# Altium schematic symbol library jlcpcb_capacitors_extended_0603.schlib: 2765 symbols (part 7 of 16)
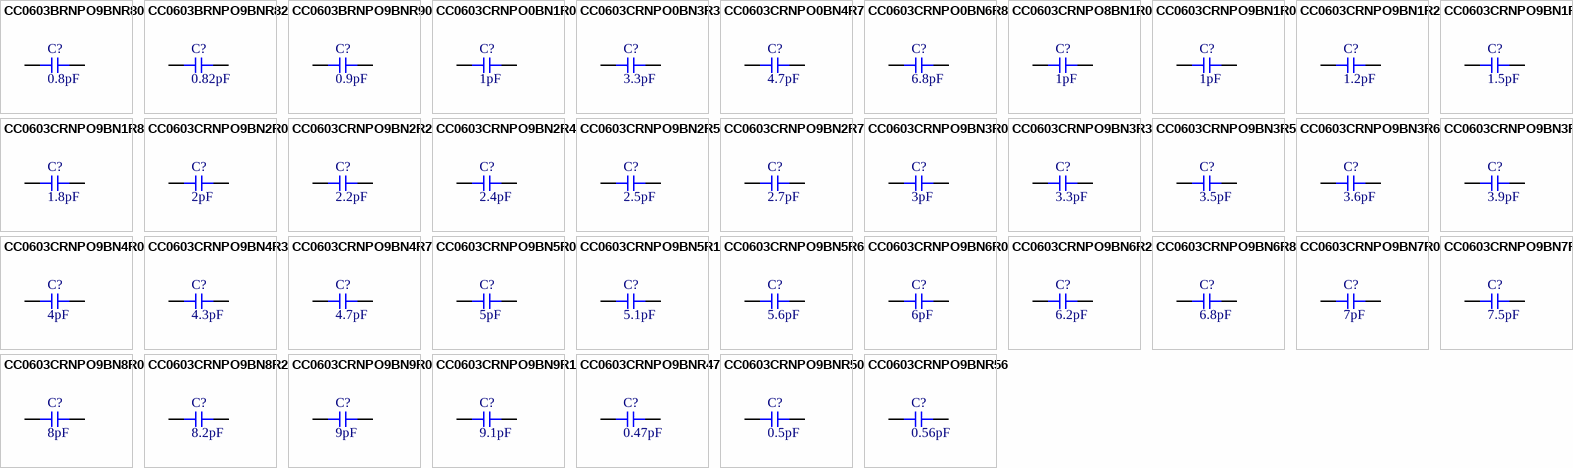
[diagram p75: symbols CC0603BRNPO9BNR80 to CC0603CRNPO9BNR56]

## CC0603CRNPO9BN2R4
designator C?  Capacitance: 2.4pF  (hidden comment: *)
Capacitor, Ceramic (MLCC), 2.4pF, ±0.25pF, 50V, NP0, ±0.25pF, SMD 0603; Manufacturer: YAGEO; Manufacturer Part Number: CC0603CRNPO9BN2R4
footprint CAP-0603 (0603 (1608M) Capacitor)
pins: 1, 2

## CC0603CRNPO9BN2R5
designator C?  Capacitance: 2.5pF  (hidden comment: *)
Capacitor, Ceramic (MLCC), 2.5pF, ±0.25pF, 50V, NP0, ±0.25pF, SMD 0603; Manufacturer: YAGEO; Manufacturer Part Number: CC0603CRNPO9BN2R5
footprint CAP-0603 (0603 (1608M) Capacitor)
pins: 1, 2

## CC0603CRNPO9BN2R7
designator C?  Capacitance: 2.7pF  (hidden comment: *)
Capacitor, Ceramic (MLCC), 2.7pF, ±0.25pF, 50V, NP0, ±0.25pF, SMD 0603; Manufacturer: YAGEO; Manufacturer Part Number: CC0603CRNPO9BN2R7
footprint CAP-0603 (0603 (1608M) Capacitor)
pins: 1, 2

## CC0603CRNPO9BN3R0
designator C?  Capacitance: 3pF  (hidden comment: *)
Capacitor, Ceramic (MLCC), 3pF, ±0.25pF, 50V, NP0, ±0.25pF, SMD 0603; Manufacturer: YAGEO; Manufacturer Part Number: CC0603CRNPO9BN3R0
footprint CAP-0603 (0603 (1608M) Capacitor)
pins: 1, 2

## CC0603CRNPO9BN3R3
designator C?  Capacitance: 3.3pF  (hidden comment: *)
Capacitor, Ceramic (MLCC), 3.3pF, ±0.25pF, 50V, NP0, ±0.25pF, SMD 0603; Manufacturer: YAGEO; Manufacturer Part Number: CC0603CRNPO9BN3R3
footprint CAP-0603 (0603 (1608M) Capacitor)
pins: 1, 2

## CC0603CRNPO9BN3R5
designator C?  Capacitance: 3.5pF  (hidden comment: *)
Capacitor, Ceramic (MLCC), 3.5pF, ±0.25pF, 50V, NP0, ±0.25pF, SMD 0603; Manufacturer: YAGEO; Manufacturer Part Number: CC0603CRNPO9BN3R5
footprint CAP-0603 (0603 (1608M) Capacitor)
pins: 1, 2

## CC0603CRNPO9BN3R6
designator C?  Capacitance: 3.6pF  (hidden comment: *)
Capacitor, Ceramic (MLCC), 3.6pF, ±0.25pF, 50V, NP0, ±0.25pF, SMD 0603; Manufacturer: YAGEO; Manufacturer Part Number: CC0603CRNPO9BN3R6
footprint CAP-0603 (0603 (1608M) Capacitor)
pins: 1, 2

## CC0603CRNPO9BN3R9
designator C?  Capacitance: 3.9pF  (hidden comment: *)
Capacitor, Ceramic (MLCC), 3.9pF, ±0.25pF, 50V, NP0, ±0.25pF, SMD 0603; Manufacturer: YAGEO; Manufacturer Part Number: CC0603CRNPO9BN3R9
footprint CAP-0603 (0603 (1608M) Capacitor)
pins: 1, 2

## CC0603CRNPO9BN4R0
designator C?  Capacitance: 4pF  (hidden comment: *)
Capacitor, Ceramic (MLCC), 4pF, ±0.25pF, 50V, NP0, ±0.25pF, SMD 0603; Manufacturer: YAGEO; Manufacturer Part Number: CC0603CRNPO9BN4R0
footprint CAP-0603 (0603 (1608M) Capacitor)
pins: 1, 2

## CC0603CRNPO9BN4R3
designator C?  Capacitance: 4.3pF  (hidden comment: *)
Capacitor, Ceramic (MLCC), 4.3pF, ±0.25pF, 50V, NP0, ±0.25pF, SMD 0603; Manufacturer: YAGEO; Manufacturer Part Number: CC0603CRNPO9BN4R3
footprint CAP-0603 (0603 (1608M) Capacitor)
pins: 1, 2

## CC0603CRNPO9BN4R7
designator C?  Capacitance: 4.7pF  (hidden comment: *)
Capacitor, Ceramic (MLCC), 4.7pF, ±0.25pF, 50V, NP0, ±0.25pF, SMD 0603; Manufacturer: YAGEO; Manufacturer Part Number: CC0603CRNPO9BN4R7
footprint CAP-0603 (0603 (1608M) Capacitor)
pins: 1, 2

## CC0603CRNPO9BN5R0
designator C?  Capacitance: 5pF  (hidden comment: *)
Capacitor, Ceramic (MLCC), 5pF, ±0.25pF, 50V, NP0, ±0.25pF, SMD 0603; Manufacturer: YAGEO; Manufacturer Part Number: CC0603CRNPO9BN5R0
footprint CAP-0603 (0603 (1608M) Capacitor)
pins: 1, 2

## CC0603CRNPO9BN5R1
designator C?  Capacitance: 5.1pF  (hidden comment: *)
Capacitor, Ceramic (MLCC), 5.1pF, ±0.25pF, 50V, NP0, ±0.25pF, SMD 0603; Manufacturer: YAGEO; Manufacturer Part Number: CC0603CRNPO9BN5R1
footprint CAP-0603 (0603 (1608M) Capacitor)
pins: 1, 2

## CC0603CRNPO9BN5R6
designator C?  Capacitance: 5.6pF  (hidden comment: *)
Capacitor, Ceramic (MLCC), 5.6pF, ±0.25pF, 50V, NP0, ±0.25pF, SMD 0603; Manufacturer: YAGEO; Manufacturer Part Number: CC0603CRNPO9BN5R6
footprint CAP-0603 (0603 (1608M) Capacitor)
pins: 1, 2

## CC0603CRNPO9BN6R0
designator C?  Capacitance: 6pF  (hidden comment: *)
Capacitor, Ceramic (MLCC), 6pF, ±0.25pF, 50V, NP0, ±0.25pF, SMD 0603; Manufacturer: YAGEO; Manufacturer Part Number: CC0603CRNPO9BN6R0
footprint CAP-0603 (0603 (1608M) Capacitor)
pins: 1, 2

## CC0603CRNPO9BN6R2
designator C?  Capacitance: 6.2pF  (hidden comment: *)
Capacitor, Ceramic (MLCC), 6.2pF, ±0.25pF, 50V, NP0, ±0.25pF, SMD 0603; Manufacturer: YAGEO; Manufacturer Part Number: CC0603CRNPO9BN6R2
footprint CAP-0603 (0603 (1608M) Capacitor)
pins: 1, 2

## CC0603CRNPO9BN6R8
designator C?  Capacitance: 6.8pF  (hidden comment: *)
Capacitor, Ceramic (MLCC), 6.8pF, ±0.25pF, 50V, NP0, ±0.25pF, SMD 0603; Manufacturer: YAGEO; Manufacturer Part Number: CC0603CRNPO9BN6R8
footprint CAP-0603 (0603 (1608M) Capacitor)
pins: 1, 2

## CC0603CRNPO9BN7R0
designator C?  Capacitance: 7pF  (hidden comment: *)
Capacitor, Ceramic (MLCC), 7pF, ±0.25pF, 50V, NP0, ±0.25pF, SMD 0603; Manufacturer: YAGEO; Manufacturer Part Number: CC0603CRNPO9BN7R0
footprint CAP-0603 (0603 (1608M) Capacitor)
pins: 1, 2

## CC0603CRNPO9BN7R5
designator C?  Capacitance: 7.5pF  (hidden comment: *)
Capacitor, Ceramic (MLCC), 7.5pF, ±0.25pF, 50V, NP0, ±0.25pF, SMD 0603; Manufacturer: YAGEO; Manufacturer Part Number: CC0603CRNPO9BN7R5
footprint CAP-0603 (0603 (1608M) Capacitor)
pins: 1, 2

## CC0603CRNPO9BN8R0
designator C?  Capacitance: 8pF  (hidden comment: *)
Capacitor, Ceramic (MLCC), 8pF, ±0.25pF, 50V, NP0, ±0.25pF, SMD 0603; Manufacturer: YAGEO; Manufacturer Part Number: CC0603CRNPO9BN8R0
footprint CAP-0603 (0603 (1608M) Capacitor)
pins: 1, 2

## CC0603CRNPO9BN8R2
designator C?  Capacitance: 8.2pF  (hidden comment: *)
Capacitor, Ceramic (MLCC), 8.2pF, ±0.25pF, 50V, NP0, ±0.25pF, SMD 0603; Manufacturer: YAGEO; Manufacturer Part Number: CC0603CRNPO9BN8R2
footprint CAP-0603 (0603 (1608M) Capacitor)
pins: 1, 2

## CC0603CRNPO9BN9R0
designator C?  Capacitance: 9pF  (hidden comment: *)
Capacitor, Ceramic (MLCC), 9pF, ±0.25pF, 50V, NP0, ±0.25pF, SMD 0603; Manufacturer: YAGEO; Manufacturer Part Number: CC0603CRNPO9BN9R0
footprint CAP-0603 (0603 (1608M) Capacitor)
pins: 1, 2

## CC0603CRNPO9BN9R1
designator C?  Capacitance: 9.1pF  (hidden comment: *)
Capacitor, Ceramic (MLCC), 9.1pF, ±0.25pF, 50V, NP0, ±0.25pF, SMD 0603; Manufacturer: YAGEO; Manufacturer Part Number: CC0603CRNPO9BN9R1
footprint CAP-0603 (0603 (1608M) Capacitor)
pins: 1, 2

## CC0603CRNPO9BNR47
designator C?  Capacitance: 0.47pF  (hidden comment: *)
Capacitor, Ceramic (MLCC), 0.47pF, ±0.25pF, 50V, NP0, ±0.25pF, SMD 0603; Manufacturer: YAGEO; Manufacturer Part Number: CC0603CRNPO9BNR47
footprint CAP-0603 (0603 (1608M) Capacitor)
pins: 1, 2

## CC0603CRNPO9BNR50
designator C?  Capacitance: 0.5pF  (hidden comment: *)
Capacitor, Ceramic (MLCC), 0.5pF, ±0.25pF, 50V, NP0, ±0.25pF, SMD 0603; Manufacturer: YAGEO; Manufacturer Part Number: CC0603CRNPO9BNR50
footprint CAP-0603 (0603 (1608M) Capacitor)
pins: 1, 2

## CC0603CRNPO9BNR56
designator C?  Capacitance: 0.56pF  (hidden comment: *)
Capacitor, Ceramic (MLCC), 0.56pF, ±0.25pF, 50V, NP0, ±0.25pF, SMD 0603; Manufacturer: YAGEO; Manufacturer Part Number: CC0603CRNPO9BNR56
footprint CAP-0603 (0603 (1608M) Capacitor)
pins: 1, 2

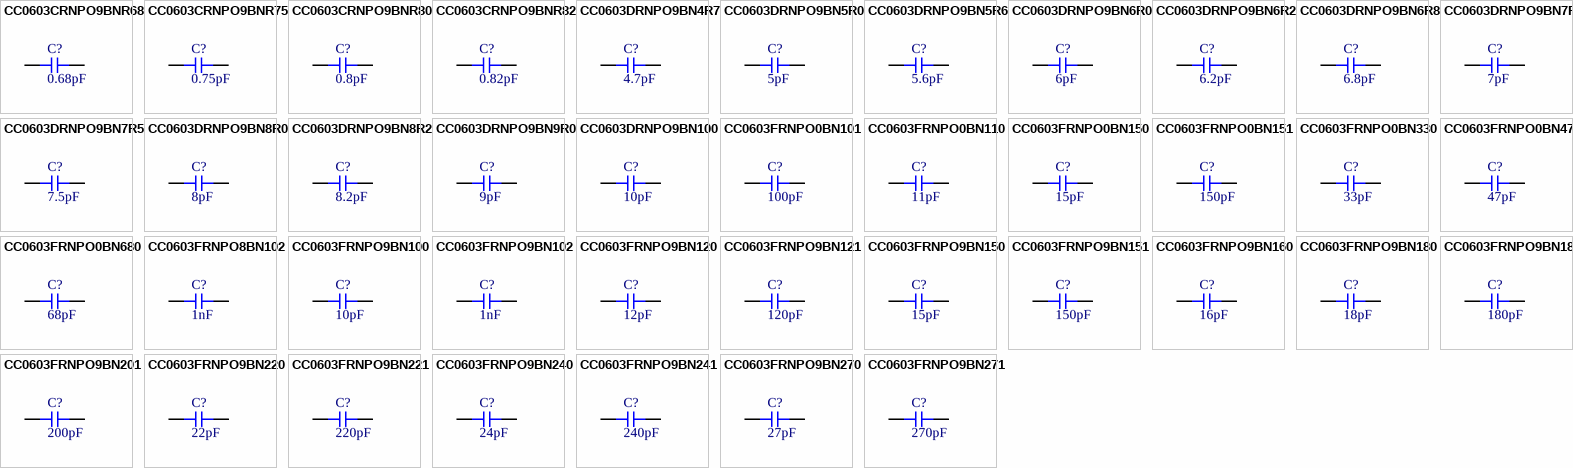
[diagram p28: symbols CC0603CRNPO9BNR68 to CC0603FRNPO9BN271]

## CC0603CRNPO9BNR68
designator C?  Capacitance: 0.68pF  (hidden comment: *)
Capacitor, Ceramic (MLCC), 0.68pF, ±0.25pF, 50V, NP0, ±0.25pF, SMD 0603; Manufacturer: YAGEO; Manufacturer Part Number: CC0603CRNPO9BNR68
footprint CAP-0603 (0603 (1608M) Capacitor)
pins: 1, 2

## CC0603CRNPO9BNR75
designator C?  Capacitance: 0.75pF  (hidden comment: *)
Capacitor, Ceramic (MLCC), 0.75pF, ±0.25pF, 50V, NP0, ±0.25pF, SMD 0603; Manufacturer: YAGEO; Manufacturer Part Number: CC0603CRNPO9BNR75
footprint CAP-0603 (0603 (1608M) Capacitor)
pins: 1, 2

## CC0603CRNPO9BNR80
designator C?  Capacitance: 0.8pF  (hidden comment: *)
Capacitor, Ceramic (MLCC), 0.8pF, ±0.25pF, 50V, NP0, ±0.25pF, SMD 0603; Manufacturer: YAGEO; Manufacturer Part Number: CC0603CRNPO9BNR80
footprint CAP-0603 (0603 (1608M) Capacitor)
pins: 1, 2

## CC0603CRNPO9BNR82
designator C?  Capacitance: 0.82pF  (hidden comment: *)
Capacitor, Ceramic (MLCC), 0.82pF, ±0.25pF, 50V, NP0, ±0.25pF, SMD 0603; Manufacturer: YAGEO; Manufacturer Part Number: CC0603CRNPO9BNR82
footprint CAP-0603 (0603 (1608M) Capacitor)
pins: 1, 2

## CC0603DRNPO9BN4R7
designator C?  Capacitance: 4.7pF  (hidden comment: *)
Capacitor, Ceramic (MLCC), 4.7pF, ±0.5pF, 50V, NP0, ±0.5pF, SMD 0603; Manufacturer: YAGEO; Manufacturer Part Number: CC0603DRNPO9BN4R7
footprint CAP-0603 (0603 (1608M) Capacitor)
pins: 1, 2

## CC0603DRNPO9BN5R0
designator C?  Capacitance: 5pF  (hidden comment: *)
Capacitor, Ceramic (MLCC), 5pF, ±0.5pF, 50V, NP0, ±0.5pF, SMD 0603; Manufacturer: YAGEO; Manufacturer Part Number: CC0603DRNPO9BN5R0
footprint CAP-0603 (0603 (1608M) Capacitor)
pins: 1, 2

## CC0603DRNPO9BN5R6
designator C?  Capacitance: 5.6pF  (hidden comment: *)
Capacitor, Ceramic (MLCC), 5.6pF, ±0.5pF, 50V, NP0, ±0.5pF, SMD 0603; Manufacturer: YAGEO; Manufacturer Part Number: CC0603DRNPO9BN5R6
footprint CAP-0603 (0603 (1608M) Capacitor)
pins: 1, 2

## CC0603DRNPO9BN6R0
designator C?  Capacitance: 6pF  (hidden comment: *)
Capacitor, Ceramic (MLCC), 6pF, ±0.5pF, 50V, NP0, ±0.5pF, SMD 0603; Manufacturer: YAGEO; Manufacturer Part Number: CC0603DRNPO9BN6R0
footprint CAP-0603 (0603 (1608M) Capacitor)
pins: 1, 2

## CC0603DRNPO9BN6R2
designator C?  Capacitance: 6.2pF  (hidden comment: *)
Capacitor, Ceramic (MLCC), 6.2pF, ±0.5pF, 50V, NP0, ±0.5pF, SMD 0603; Manufacturer: YAGEO; Manufacturer Part Number: CC0603DRNPO9BN6R2
footprint CAP-0603 (0603 (1608M) Capacitor)
pins: 1, 2

## CC0603DRNPO9BN6R8
designator C?  Capacitance: 6.8pF  (hidden comment: *)
Capacitor, Ceramic (MLCC), 6.8pF, ±0.5pF, 50V, NP0, ±0.5pF, SMD 0603; Manufacturer: YAGEO; Manufacturer Part Number: CC0603DRNPO9BN6R8
footprint CAP-0603 (0603 (1608M) Capacitor)
pins: 1, 2

## CC0603DRNPO9BN7R0
designator C?  Capacitance: 7pF  (hidden comment: *)
Capacitor, Ceramic (MLCC), 7pF, ±0.5pF, 50V, NP0, ±0.5pF, SMD 0603; Manufacturer: YAGEO; Manufacturer Part Number: CC0603DRNPO9BN7R0
footprint CAP-0603 (0603 (1608M) Capacitor)
pins: 1, 2

## CC0603DRNPO9BN7R5
designator C?  Capacitance: 7.5pF  (hidden comment: *)
Capacitor, Ceramic (MLCC), 7.5pF, ±0.5pF, 50V, NP0, ±0.5pF, SMD 0603; Manufacturer: YAGEO; Manufacturer Part Number: CC0603DRNPO9BN7R5
footprint CAP-0603 (0603 (1608M) Capacitor)
pins: 1, 2

## CC0603DRNPO9BN8R0
designator C?  Capacitance: 8pF  (hidden comment: *)
Capacitor, Ceramic (MLCC), 8pF, ±0.5pF, 50V, NP0, ±0.5pF, SMD 0603; Manufacturer: YAGEO; Manufacturer Part Number: CC0603DRNPO9BN8R0
footprint CAP-0603 (0603 (1608M) Capacitor)
pins: 1, 2

## CC0603DRNPO9BN8R2
designator C?  Capacitance: 8.2pF  (hidden comment: *)
Capacitor, Ceramic (MLCC), 8.2pF, ±0.5pF, 50V, NP0, ±0.5pF, SMD 0603; Manufacturer: YAGEO; Manufacturer Part Number: CC0603DRNPO9BN8R2
footprint CAP-0603 (0603 (1608M) Capacitor)
pins: 1, 2

## CC0603DRNPO9BN9R0
designator C?  Capacitance: 9pF  (hidden comment: *)
Capacitor, Ceramic (MLCC), 9pF, ±0.5pF, 50V, NP0, ±0.5pF, SMD 0603; Manufacturer: YAGEO; Manufacturer Part Number: CC0603DRNPO9BN9R0
footprint CAP-0603 (0603 (1608M) Capacitor)
pins: 1, 2

## CC0603DRNPO9BN100
designator C?  Capacitance: 10pF  (hidden comment: *)
Capacitor, Ceramic (MLCC), 10pF, ±0.5pF, 50V, NP0, ±0.5pF, SMD 0603; Manufacturer: YAGEO; Manufacturer Part Number: CC0603DRNPO9BN100
footprint CAP-0603 (0603 (1608M) Capacitor)
pins: 1, 2

## CC0603FRNPO0BN101
designator C?  Capacitance: 100pF  (hidden comment: *)
Capacitor, Ceramic (MLCC), 100pF, ±1%, 100V, NP0, ±1%, SMD 0603; Manufacturer: YAGEO; Manufacturer Part Number: CC0603FRNPO0BN101
footprint CAP-0603 (0603 (1608M) Capacitor)
pins: 1, 2

## CC0603FRNPO0BN110
designator C?  Capacitance: 11pF  (hidden comment: *)
Capacitor, Ceramic (MLCC), 11pF, ±1%, 100V, NP0, ±1%, SMD 0603; Manufacturer: YAGEO; Manufacturer Part Number: CC0603FRNPO0BN110
footprint CAP-0603 (0603 (1608M) Capacitor)
pins: 1, 2

## CC0603FRNPO0BN150
designator C?  Capacitance: 15pF  (hidden comment: *)
Capacitor, Ceramic (MLCC), 15pF, ±1%, 100V, NP0, ±1%, SMD 0603; Manufacturer: YAGEO; Manufacturer Part Number: CC0603FRNPO0BN150
footprint CAP-0603 (0603 (1608M) Capacitor)
pins: 1, 2

## CC0603FRNPO0BN151
designator C?  Capacitance: 150pF  (hidden comment: *)
Capacitor, Ceramic (MLCC), 150pF, ±1%, 100V, NP0, ±1%, SMD 0603; Manufacturer: YAGEO; Manufacturer Part Number: CC0603FRNPO0BN151
footprint CAP-0603 (0603 (1608M) Capacitor)
pins: 1, 2

## CC0603FRNPO0BN330
designator C?  Capacitance: 33pF  (hidden comment: *)
Capacitor, Ceramic (MLCC), 33pF, ±1%, 100V, NP0, ±1%, SMD 0603; Manufacturer: YAGEO; Manufacturer Part Number: CC0603FRNPO0BN330
footprint CAP-0603 (0603 (1608M) Capacitor)
pins: 1, 2

## CC0603FRNPO0BN470
designator C?  Capacitance: 47pF  (hidden comment: *)
Capacitor, Ceramic (MLCC), 47pF, ±1%, 100V, NP0, ±1%, SMD 0603; Manufacturer: YAGEO; Manufacturer Part Number: CC0603FRNPO0BN470
footprint CAP-0603 (0603 (1608M) Capacitor)
pins: 1, 2

## CC0603FRNPO0BN680
designator C?  Capacitance: 68pF  (hidden comment: *)
Capacitor, Ceramic (MLCC), 68pF, ±1%, 100V, NP0, ±1%, SMD 0603; Manufacturer: YAGEO; Manufacturer Part Number: CC0603FRNPO0BN680
footprint CAP-0603 (0603 (1608M) Capacitor)
pins: 1, 2

## CC0603FRNPO8BN102
designator C?  Capacitance: 1nF  (hidden comment: *)
Capacitor, Ceramic (MLCC), 1nF, ±1%, 25V, NP0, ±1%, SMD 0603; Manufacturer: YAGEO; Manufacturer Part Number: CC0603FRNPO8BN102
footprint CAP-0603 (0603 (1608M) Capacitor)
pins: 1, 2

## CC0603FRNPO9BN100
designator C?  Capacitance: 10pF  (hidden comment: *)
Capacitor, Ceramic (MLCC), 10pF, ±1%, 50V, NP0, ±1%, SMD 0603; Manufacturer: YAGEO; Manufacturer Part Number: CC0603FRNPO9BN100
footprint CAP-0603 (0603 (1608M) Capacitor)
pins: 1, 2

## CC0603FRNPO9BN102
designator C?  Capacitance: 1nF  (hidden comment: *)
Capacitor, Ceramic (MLCC), 1nF, ±1%, 50V, NP0, ±1%, SMD 0603; Manufacturer: YAGEO; Manufacturer Part Number: CC0603FRNPO9BN102
footprint CAP-0603 (0603 (1608M) Capacitor)
pins: 1, 2

## CC0603FRNPO9BN120
designator C?  Capacitance: 12pF  (hidden comment: *)
Capacitor, Ceramic (MLCC), 12pF, ±1%, 50V, NP0, ±1%, SMD 0603; Manufacturer: YAGEO; Manufacturer Part Number: CC0603FRNPO9BN120
footprint CAP-0603 (0603 (1608M) Capacitor)
pins: 1, 2

## CC0603FRNPO9BN121
designator C?  Capacitance: 120pF  (hidden comment: *)
Capacitor, Ceramic (MLCC), 120pF, ±1%, 50V, NP0, ±1%, SMD 0603; Manufacturer: YAGEO; Manufacturer Part Number: CC0603FRNPO9BN121
footprint CAP-0603 (0603 (1608M) Capacitor)
pins: 1, 2

## CC0603FRNPO9BN150
designator C?  Capacitance: 15pF  (hidden comment: *)
Capacitor, Ceramic (MLCC), 15pF, ±1%, 50V, NP0, ±1%, SMD 0603; Manufacturer: YAGEO; Manufacturer Part Number: CC0603FRNPO9BN150
footprint CAP-0603 (0603 (1608M) Capacitor)
pins: 1, 2

## CC0603FRNPO9BN151
designator C?  Capacitance: 150pF  (hidden comment: *)
Capacitor, Ceramic (MLCC), 150pF, ±1%, 50V, NP0, ±1%, SMD 0603; Manufacturer: YAGEO; Manufacturer Part Number: CC0603FRNPO9BN151
footprint CAP-0603 (0603 (1608M) Capacitor)
pins: 1, 2

## CC0603FRNPO9BN160
designator C?  Capacitance: 16pF  (hidden comment: *)
Capacitor, Ceramic (MLCC), 16pF, ±1%, 50V, NP0, ±1%, SMD 0603; Manufacturer: YAGEO; Manufacturer Part Number: CC0603FRNPO9BN160
footprint CAP-0603 (0603 (1608M) Capacitor)
pins: 1, 2

## CC0603FRNPO9BN180
designator C?  Capacitance: 18pF  (hidden comment: *)
Capacitor, Ceramic (MLCC), 18pF, ±1%, 50V, NP0, ±1%, SMD 0603; Manufacturer: YAGEO; Manufacturer Part Number: CC0603FRNPO9BN180
footprint CAP-0603 (0603 (1608M) Capacitor)
pins: 1, 2

## CC0603FRNPO9BN181
designator C?  Capacitance: 180pF  (hidden comment: *)
Capacitor, Ceramic (MLCC), 180pF, ±1%, 50V, NP0, ±1%, SMD 0603; Manufacturer: YAGEO; Manufacturer Part Number: CC0603FRNPO9BN181
footprint CAP-0603 (0603 (1608M) Capacitor)
pins: 1, 2

## CC0603FRNPO9BN201
designator C?  Capacitance: 200pF  (hidden comment: *)
Capacitor, Ceramic (MLCC), 200pF, ±1%, 50V, NP0, ±1%, SMD 0603; Manufacturer: YAGEO; Manufacturer Part Number: CC0603FRNPO9BN201
footprint CAP-0603 (0603 (1608M) Capacitor)
pins: 1, 2

## CC0603FRNPO9BN220
designator C?  Capacitance: 22pF  (hidden comment: *)
Capacitor, Ceramic (MLCC), 22pF, ±1%, 50V, NP0, ±1%, SMD 0603; Manufacturer: YAGEO; Manufacturer Part Number: CC0603FRNPO9BN220
footprint CAP-0603 (0603 (1608M) Capacitor)
pins: 1, 2

## CC0603FRNPO9BN221
designator C?  Capacitance: 220pF  (hidden comment: *)
Capacitor, Ceramic (MLCC), 220pF, ±1%, 50V, NP0, ±1%, SMD 0603; Manufacturer: YAGEO; Manufacturer Part Number: CC0603FRNPO9BN221
footprint CAP-0603 (0603 (1608M) Capacitor)
pins: 1, 2

## CC0603FRNPO9BN240
designator C?  Capacitance: 24pF  (hidden comment: *)
Capacitor, Ceramic (MLCC), 24pF, ±1%, 50V, NP0, ±1%, SMD 0603; Manufacturer: YAGEO; Manufacturer Part Number: CC0603FRNPO9BN240
footprint CAP-0603 (0603 (1608M) Capacitor)
pins: 1, 2

## CC0603FRNPO9BN241
designator C?  Capacitance: 240pF  (hidden comment: *)
Capacitor, Ceramic (MLCC), 240pF, ±1%, 50V, NP0, ±1%, SMD 0603; Manufacturer: YAGEO; Manufacturer Part Number: CC0603FRNPO9BN241
footprint CAP-0603 (0603 (1608M) Capacitor)
pins: 1, 2

## CC0603FRNPO9BN270
designator C?  Capacitance: 27pF  (hidden comment: *)
Capacitor, Ceramic (MLCC), 27pF, ±1%, 50V, NP0, ±1%, SMD 0603; Manufacturer: YAGEO; Manufacturer Part Number: CC0603FRNPO9BN270
footprint CAP-0603 (0603 (1608M) Capacitor)
pins: 1, 2

## CC0603FRNPO9BN271
designator C?  Capacitance: 270pF  (hidden comment: *)
Capacitor, Ceramic (MLCC), 270pF, ±1%, 50V, NP0, ±1%, SMD 0603; Manufacturer: YAGEO; Manufacturer Part Number: CC0603FRNPO9BN271
footprint CAP-0603 (0603 (1608M) Capacitor)
pins: 1, 2

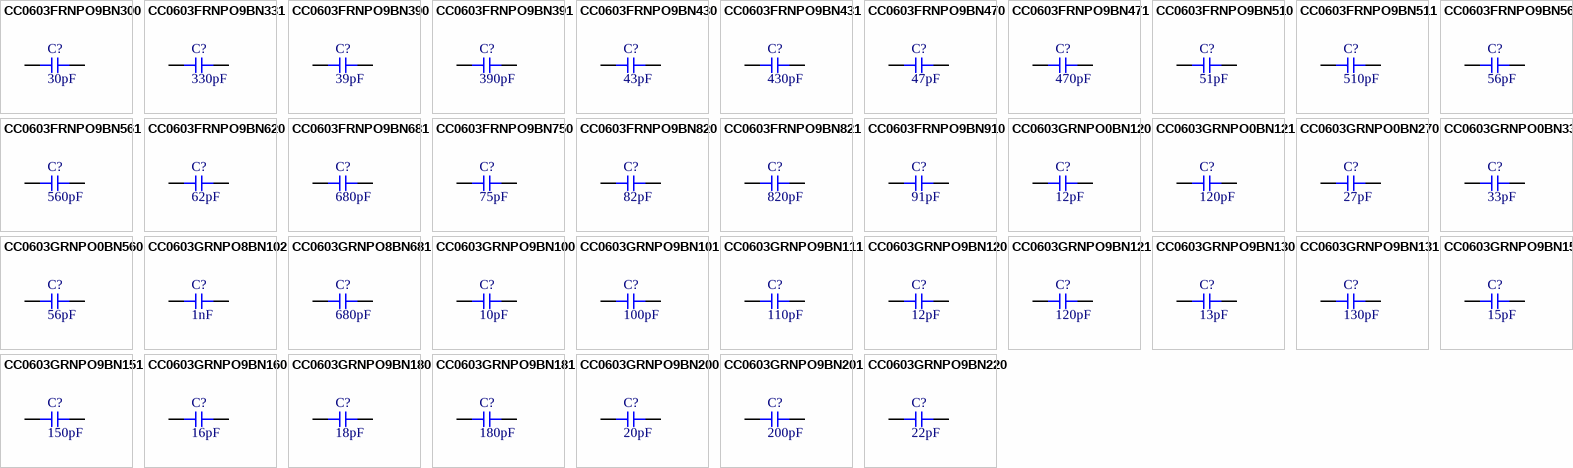
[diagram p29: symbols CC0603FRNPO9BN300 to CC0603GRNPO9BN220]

## CC0603FRNPO9BN300
designator C?  Capacitance: 30pF  (hidden comment: *)
Capacitor, Ceramic (MLCC), 30pF, ±1%, 50V, NP0, ±1%, SMD 0603; Manufacturer: YAGEO; Manufacturer Part Number: CC0603FRNPO9BN300
footprint CAP-0603 (0603 (1608M) Capacitor)
pins: 1, 2

## CC0603FRNPO9BN331
designator C?  Capacitance: 330pF  (hidden comment: *)
Capacitor, Ceramic (MLCC), 330pF, ±1%, 50V, NP0, ±1%, SMD 0603; Manufacturer: YAGEO; Manufacturer Part Number: CC0603FRNPO9BN331
footprint CAP-0603 (0603 (1608M) Capacitor)
pins: 1, 2

## CC0603FRNPO9BN390
designator C?  Capacitance: 39pF  (hidden comment: *)
Capacitor, Ceramic (MLCC), 39pF, ±1%, 50V, NP0, ±1%, SMD 0603; Manufacturer: YAGEO; Manufacturer Part Number: CC0603FRNPO9BN390
footprint CAP-0603 (0603 (1608M) Capacitor)
pins: 1, 2

## CC0603FRNPO9BN391
designator C?  Capacitance: 390pF  (hidden comment: *)
Capacitor, Ceramic (MLCC), 390pF, ±1%, 50V, NP0, ±1%, SMD 0603; Manufacturer: YAGEO; Manufacturer Part Number: CC0603FRNPO9BN391
footprint CAP-0603 (0603 (1608M) Capacitor)
pins: 1, 2

## CC0603FRNPO9BN430
designator C?  Capacitance: 43pF  (hidden comment: *)
Capacitor, Ceramic (MLCC), 43pF, ±1%, 50V, NP0, ±1%, SMD 0603; Manufacturer: YAGEO; Manufacturer Part Number: CC0603FRNPO9BN430
footprint CAP-0603 (0603 (1608M) Capacitor)
pins: 1, 2

## CC0603FRNPO9BN431
designator C?  Capacitance: 430pF  (hidden comment: *)
Capacitor, Ceramic (MLCC), 430pF, ±1%, 50V, NP0, ±1%, SMD 0603; Manufacturer: YAGEO; Manufacturer Part Number: CC0603FRNPO9BN431
footprint CAP-0603 (0603 (1608M) Capacitor)
pins: 1, 2

## CC0603FRNPO9BN470
designator C?  Capacitance: 47pF  (hidden comment: *)
Capacitor, Ceramic (MLCC), 47pF, ±1%, 50V, NP0, ±1%, SMD 0603; Manufacturer: YAGEO; Manufacturer Part Number: CC0603FRNPO9BN470
footprint CAP-0603 (0603 (1608M) Capacitor)
pins: 1, 2

## CC0603FRNPO9BN471
designator C?  Capacitance: 470pF  (hidden comment: *)
Capacitor, Ceramic (MLCC), 470pF, ±1%, 50V, NP0, ±1%, SMD 0603; Manufacturer: YAGEO; Manufacturer Part Number: CC0603FRNPO9BN471
footprint CAP-0603 (0603 (1608M) Capacitor)
pins: 1, 2

## CC0603FRNPO9BN510
designator C?  Capacitance: 51pF  (hidden comment: *)
Capacitor, Ceramic (MLCC), 51pF, ±1%, 50V, NP0, ±1%, SMD 0603; Manufacturer: YAGEO; Manufacturer Part Number: CC0603FRNPO9BN510
footprint CAP-0603 (0603 (1608M) Capacitor)
pins: 1, 2

## CC0603FRNPO9BN511
designator C?  Capacitance: 510pF  (hidden comment: *)
Capacitor, Ceramic (MLCC), 510pF, ±1%, 50V, NP0, ±1%, SMD 0603; Manufacturer: YAGEO; Manufacturer Part Number: CC0603FRNPO9BN511
footprint CAP-0603 (0603 (1608M) Capacitor)
pins: 1, 2

## CC0603FRNPO9BN560
designator C?  Capacitance: 56pF  (hidden comment: *)
Capacitor, Ceramic (MLCC), 56pF, ±1%, 50V, NP0, ±1%, SMD 0603; Manufacturer: YAGEO; Manufacturer Part Number: CC0603FRNPO9BN560
footprint CAP-0603 (0603 (1608M) Capacitor)
pins: 1, 2

## CC0603FRNPO9BN561
designator C?  Capacitance: 560pF  (hidden comment: *)
Capacitor, Ceramic (MLCC), 560pF, ±1%, 50V, NP0, ±1%, SMD 0603; Manufacturer: YAGEO; Manufacturer Part Number: CC0603FRNPO9BN561
footprint CAP-0603 (0603 (1608M) Capacitor)
pins: 1, 2

## CC0603FRNPO9BN620
designator C?  Capacitance: 62pF  (hidden comment: *)
Capacitor, Ceramic (MLCC), 62pF, ±1%, 50V, NP0, ±1%, SMD 0603; Manufacturer: YAGEO; Manufacturer Part Number: CC0603FRNPO9BN620
footprint CAP-0603 (0603 (1608M) Capacitor)
pins: 1, 2

## CC0603FRNPO9BN681
designator C?  Capacitance: 680pF  (hidden comment: *)
Capacitor, Ceramic (MLCC), 680pF, ±1%, 50V, NP0, ±1%, SMD 0603; Manufacturer: YAGEO; Manufacturer Part Number: CC0603FRNPO9BN681
footprint CAP-0603 (0603 (1608M) Capacitor)
pins: 1, 2

## CC0603FRNPO9BN750
designator C?  Capacitance: 75pF  (hidden comment: *)
Capacitor, Ceramic (MLCC), 75pF, ±1%, 50V, NP0, ±1%, SMD 0603; Manufacturer: YAGEO; Manufacturer Part Number: CC0603FRNPO9BN750
footprint CAP-0603 (0603 (1608M) Capacitor)
pins: 1, 2

## CC0603FRNPO9BN820
designator C?  Capacitance: 82pF  (hidden comment: *)
Capacitor, Ceramic (MLCC), 82pF, ±1%, 50V, NP0, ±1%, SMD 0603; Manufacturer: YAGEO; Manufacturer Part Number: CC0603FRNPO9BN820
footprint CAP-0603 (0603 (1608M) Capacitor)
pins: 1, 2

## CC0603FRNPO9BN821
designator C?  Capacitance: 820pF  (hidden comment: *)
Capacitor, Ceramic (MLCC), 820pF, ±1%, 50V, NP0, ±1%, SMD 0603; Manufacturer: YAGEO; Manufacturer Part Number: CC0603FRNPO9BN821
footprint CAP-0603 (0603 (1608M) Capacitor)
pins: 1, 2

## CC0603FRNPO9BN910
designator C?  Capacitance: 91pF  (hidden comment: *)
Capacitor, Ceramic (MLCC), 91pF, ±1%, 50V, NP0, ±1%, SMD 0603; Manufacturer: YAGEO; Manufacturer Part Number: CC0603FRNPO9BN910
footprint CAP-0603 (0603 (1608M) Capacitor)
pins: 1, 2

## CC0603GRNPO0BN120
designator C?  Capacitance: 12pF  (hidden comment: *)
Capacitor, Ceramic (MLCC), 12pF, ±2%, 100V, NP0, ±2%, SMD 0603; Manufacturer: YAGEO; Manufacturer Part Number: CC0603GRNPO0BN120
footprint CAP-0603 (0603 (1608M) Capacitor)
pins: 1, 2

## CC0603GRNPO0BN121
designator C?  Capacitance: 120pF  (hidden comment: *)
Capacitor, Ceramic (MLCC), 120pF, ±2%, 100V, NP0, ±2%, SMD 0603; Manufacturer: YAGEO; Manufacturer Part Number: CC0603GRNPO0BN121
footprint CAP-0603 (0603 (1608M) Capacitor)
pins: 1, 2

## CC0603GRNPO0BN270
designator C?  Capacitance: 27pF  (hidden comment: *)
Capacitor, Ceramic (MLCC), 27pF, ±2%, 100V, NP0, ±2%, SMD 0603; Manufacturer: YAGEO; Manufacturer Part Number: CC0603GRNPO0BN270
footprint CAP-0603 (0603 (1608M) Capacitor)
pins: 1, 2

## CC0603GRNPO0BN330
designator C?  Capacitance: 33pF  (hidden comment: *)
Capacitor, Ceramic (MLCC), 33pF, ±2%, 100V, NP0, ±2%, SMD 0603; Manufacturer: YAGEO; Manufacturer Part Number: CC0603GRNPO0BN330
footprint CAP-0603 (0603 (1608M) Capacitor)
pins: 1, 2

## CC0603GRNPO0BN560
designator C?  Capacitance: 56pF  (hidden comment: *)
Capacitor, Ceramic (MLCC), 56pF, ±2%, 100V, NP0, ±2%, SMD 0603; Manufacturer: YAGEO; Manufacturer Part Number: CC0603GRNPO0BN560
footprint CAP-0603 (0603 (1608M) Capacitor)
pins: 1, 2

## CC0603GRNPO8BN102
designator C?  Capacitance: 1nF  (hidden comment: *)
Capacitor, Ceramic (MLCC), 1nF, ±2%, 25V, NP0, ±2%, SMD 0603; Manufacturer: YAGEO; Manufacturer Part Number: CC0603GRNPO8BN102
footprint CAP-0603 (0603 (1608M) Capacitor)
pins: 1, 2

## CC0603GRNPO8BN681
designator C?  Capacitance: 680pF  (hidden comment: *)
Capacitor, Ceramic (MLCC), 680pF, ±2%, 25V, NP0, ±2%, SMD 0603; Manufacturer: YAGEO; Manufacturer Part Number: CC0603GRNPO8BN681
footprint CAP-0603 (0603 (1608M) Capacitor)
pins: 1, 2

## CC0603GRNPO9BN100
designator C?  Capacitance: 10pF  (hidden comment: *)
Capacitor, Ceramic (MLCC), 10pF, ±2%, 50V, NP0, ±2%, SMD 0603; Manufacturer: YAGEO; Manufacturer Part Number: CC0603GRNPO9BN100
footprint CAP-0603 (0603 (1608M) Capacitor)
pins: 1, 2

## CC0603GRNPO9BN101
designator C?  Capacitance: 100pF  (hidden comment: *)
Capacitor, Ceramic (MLCC), 100pF, ±2%, 50V, NP0, ±2%, SMD 0603; Manufacturer: YAGEO; Manufacturer Part Number: CC0603GRNPO9BN101
footprint CAP-0603 (0603 (1608M) Capacitor)
pins: 1, 2

## CC0603GRNPO9BN111
designator C?  Capacitance: 110pF  (hidden comment: *)
Capacitor, Ceramic (MLCC), 110pF, ±2%, 50V, NP0, ±2%, SMD 0603; Manufacturer: YAGEO; Manufacturer Part Number: CC0603GRNPO9BN111
footprint CAP-0603 (0603 (1608M) Capacitor)
pins: 1, 2

## CC0603GRNPO9BN120
designator C?  Capacitance: 12pF  (hidden comment: *)
Capacitor, Ceramic (MLCC), 12pF, ±2%, 50V, NP0, ±2%, SMD 0603; Manufacturer: YAGEO; Manufacturer Part Number: CC0603GRNPO9BN120
footprint CAP-0603 (0603 (1608M) Capacitor)
pins: 1, 2

## CC0603GRNPO9BN121
designator C?  Capacitance: 120pF  (hidden comment: *)
Capacitor, Ceramic (MLCC), 120pF, ±2%, 50V, NP0, ±2%, SMD 0603; Manufacturer: YAGEO; Manufacturer Part Number: CC0603GRNPO9BN121
footprint CAP-0603 (0603 (1608M) Capacitor)
pins: 1, 2

## CC0603GRNPO9BN130
designator C?  Capacitance: 13pF  (hidden comment: *)
Capacitor, Ceramic (MLCC), 13pF, ±2%, 50V, NP0, ±2%, SMD 0603; Manufacturer: YAGEO; Manufacturer Part Number: CC0603GRNPO9BN130
footprint CAP-0603 (0603 (1608M) Capacitor)
pins: 1, 2

## CC0603GRNPO9BN131
designator C?  Capacitance: 130pF  (hidden comment: *)
Capacitor, Ceramic (MLCC), 130pF, ±2%, 50V, NP0, ±2%, SMD 0603; Manufacturer: YAGEO; Manufacturer Part Number: CC0603GRNPO9BN131
footprint CAP-0603 (0603 (1608M) Capacitor)
pins: 1, 2

## CC0603GRNPO9BN150
designator C?  Capacitance: 15pF  (hidden comment: *)
Capacitor, Ceramic (MLCC), 15pF, ±2%, 50V, NP0, ±2%, SMD 0603; Manufacturer: YAGEO; Manufacturer Part Number: CC0603GRNPO9BN150
footprint CAP-0603 (0603 (1608M) Capacitor)
pins: 1, 2

## CC0603GRNPO9BN151
designator C?  Capacitance: 150pF  (hidden comment: *)
Capacitor, Ceramic (MLCC), 150pF, ±2%, 50V, NP0, ±2%, SMD 0603; Manufacturer: YAGEO; Manufacturer Part Number: CC0603GRNPO9BN151
footprint CAP-0603 (0603 (1608M) Capacitor)
pins: 1, 2

## CC0603GRNPO9BN160
designator C?  Capacitance: 16pF  (hidden comment: *)
Capacitor, Ceramic (MLCC), 16pF, ±2%, 50V, NP0, ±2%, SMD 0603; Manufacturer: YAGEO; Manufacturer Part Number: CC0603GRNPO9BN160
footprint CAP-0603 (0603 (1608M) Capacitor)
pins: 1, 2

## CC0603GRNPO9BN180
designator C?  Capacitance: 18pF  (hidden comment: *)
Capacitor, Ceramic (MLCC), 18pF, ±2%, 50V, NP0, ±2%, SMD 0603; Manufacturer: YAGEO; Manufacturer Part Number: CC0603GRNPO9BN180
footprint CAP-0603 (0603 (1608M) Capacitor)
pins: 1, 2

## CC0603GRNPO9BN181
designator C?  Capacitance: 180pF  (hidden comment: *)
Capacitor, Ceramic (MLCC), 180pF, ±2%, 50V, NP0, ±2%, SMD 0603; Manufacturer: YAGEO; Manufacturer Part Number: CC0603GRNPO9BN181
footprint CAP-0603 (0603 (1608M) Capacitor)
pins: 1, 2

## CC0603GRNPO9BN200
designator C?  Capacitance: 20pF  (hidden comment: *)
Capacitor, Ceramic (MLCC), 20pF, ±2%, 50V, NP0, ±2%, SMD 0603; Manufacturer: YAGEO; Manufacturer Part Number: CC0603GRNPO9BN200
footprint CAP-0603 (0603 (1608M) Capacitor)
pins: 1, 2

## CC0603GRNPO9BN201
designator C?  Capacitance: 200pF  (hidden comment: *)
Capacitor, Ceramic (MLCC), 200pF, ±2%, 50V, NP0, ±2%, SMD 0603; Manufacturer: YAGEO; Manufacturer Part Number: CC0603GRNPO9BN201
footprint CAP-0603 (0603 (1608M) Capacitor)
pins: 1, 2

## CC0603GRNPO9BN220
designator C?  Capacitance: 22pF  (hidden comment: *)
Capacitor, Ceramic (MLCC), 22pF, ±2%, 50V, NP0, ±2%, SMD 0603; Manufacturer: YAGEO; Manufacturer Part Number: CC0603GRNPO9BN220
footprint CAP-0603 (0603 (1608M) Capacitor)
pins: 1, 2

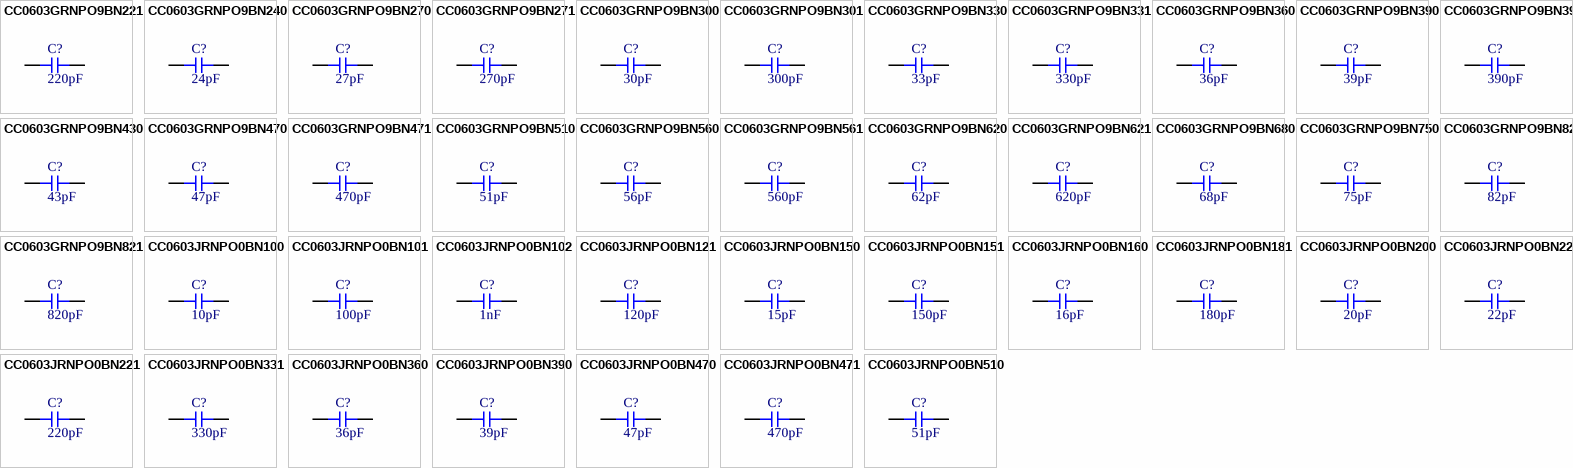
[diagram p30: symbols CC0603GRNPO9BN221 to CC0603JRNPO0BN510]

## CC0603GRNPO9BN221
designator C?  Capacitance: 220pF  (hidden comment: *)
Capacitor, Ceramic (MLCC), 220pF, ±2%, 50V, NP0, ±2%, SMD 0603; Manufacturer: YAGEO; Manufacturer Part Number: CC0603GRNPO9BN221
footprint CAP-0603 (0603 (1608M) Capacitor)
pins: 1, 2

## CC0603GRNPO9BN240
designator C?  Capacitance: 24pF  (hidden comment: *)
Capacitor, Ceramic (MLCC), 24pF, ±2%, 50V, NP0, ±2%, SMD 0603; Manufacturer: YAGEO; Manufacturer Part Number: CC0603GRNPO9BN240
footprint CAP-0603 (0603 (1608M) Capacitor)
pins: 1, 2

## CC0603GRNPO9BN270
designator C?  Capacitance: 27pF  (hidden comment: *)
Capacitor, Ceramic (MLCC), 27pF, ±2%, 50V, NP0, ±2%, SMD 0603; Manufacturer: YAGEO; Manufacturer Part Number: CC0603GRNPO9BN270
footprint CAP-0603 (0603 (1608M) Capacitor)
pins: 1, 2

## CC0603GRNPO9BN271
designator C?  Capacitance: 270pF  (hidden comment: *)
Capacitor, Ceramic (MLCC), 270pF, ±2%, 50V, NP0, ±2%, SMD 0603; Manufacturer: YAGEO; Manufacturer Part Number: CC0603GRNPO9BN271
footprint CAP-0603 (0603 (1608M) Capacitor)
pins: 1, 2

## CC0603GRNPO9BN300
designator C?  Capacitance: 30pF  (hidden comment: *)
Capacitor, Ceramic (MLCC), 30pF, ±2%, 50V, NP0, ±2%, SMD 0603; Manufacturer: YAGEO; Manufacturer Part Number: CC0603GRNPO9BN300
footprint CAP-0603 (0603 (1608M) Capacitor)
pins: 1, 2

## CC0603GRNPO9BN301
designator C?  Capacitance: 300pF  (hidden comment: *)
Capacitor, Ceramic (MLCC), 300pF, ±2%, 50V, NP0, ±2%, SMD 0603; Manufacturer: YAGEO; Manufacturer Part Number: CC0603GRNPO9BN301
footprint CAP-0603 (0603 (1608M) Capacitor)
pins: 1, 2

## CC0603GRNPO9BN330
designator C?  Capacitance: 33pF  (hidden comment: *)
Capacitor, Ceramic (MLCC), 33pF, ±2%, 50V, NP0, ±2%, SMD 0603; Manufacturer: YAGEO; Manufacturer Part Number: CC0603GRNPO9BN330
footprint CAP-0603 (0603 (1608M) Capacitor)
pins: 1, 2

## CC0603GRNPO9BN331
designator C?  Capacitance: 330pF  (hidden comment: *)
Capacitor, Ceramic (MLCC), 330pF, ±2%, 50V, NP0, ±2%, SMD 0603; Manufacturer: YAGEO; Manufacturer Part Number: CC0603GRNPO9BN331
footprint CAP-0603 (0603 (1608M) Capacitor)
pins: 1, 2

## CC0603GRNPO9BN360
designator C?  Capacitance: 36pF  (hidden comment: *)
Capacitor, Ceramic (MLCC), 36pF, ±2%, 50V, NP0, ±2%, SMD 0603; Manufacturer: YAGEO; Manufacturer Part Number: CC0603GRNPO9BN360
footprint CAP-0603 (0603 (1608M) Capacitor)
pins: 1, 2

## CC0603GRNPO9BN390
designator C?  Capacitance: 39pF  (hidden comment: *)
Capacitor, Ceramic (MLCC), 39pF, ±2%, 50V, NP0, ±2%, SMD 0603; Manufacturer: YAGEO; Manufacturer Part Number: CC0603GRNPO9BN390
footprint CAP-0603 (0603 (1608M) Capacitor)
pins: 1, 2

## CC0603GRNPO9BN391
designator C?  Capacitance: 390pF  (hidden comment: *)
Capacitor, Ceramic (MLCC), 390pF, ±2%, 50V, NP0, ±2%, SMD 0603; Manufacturer: YAGEO; Manufacturer Part Number: CC0603GRNPO9BN391
footprint CAP-0603 (0603 (1608M) Capacitor)
pins: 1, 2

## CC0603GRNPO9BN430
designator C?  Capacitance: 43pF  (hidden comment: *)
Capacitor, Ceramic (MLCC), 43pF, ±2%, 50V, NP0, ±2%, SMD 0603; Manufacturer: YAGEO; Manufacturer Part Number: CC0603GRNPO9BN430
footprint CAP-0603 (0603 (1608M) Capacitor)
pins: 1, 2

## CC0603GRNPO9BN470
designator C?  Capacitance: 47pF  (hidden comment: *)
Capacitor, Ceramic (MLCC), 47pF, ±2%, 50V, NP0, ±2%, SMD 0603; Manufacturer: YAGEO; Manufacturer Part Number: CC0603GRNPO9BN470
footprint CAP-0603 (0603 (1608M) Capacitor)
pins: 1, 2

## CC0603GRNPO9BN471
designator C?  Capacitance: 470pF  (hidden comment: *)
Capacitor, Ceramic (MLCC), 470pF, ±2%, 50V, NP0, ±2%, SMD 0603; Manufacturer: YAGEO; Manufacturer Part Number: CC0603GRNPO9BN471
footprint CAP-0603 (0603 (1608M) Capacitor)
pins: 1, 2

## CC0603GRNPO9BN510
designator C?  Capacitance: 51pF  (hidden comment: *)
Capacitor, Ceramic (MLCC), 51pF, ±2%, 50V, NP0, ±2%, SMD 0603; Manufacturer: YAGEO; Manufacturer Part Number: CC0603GRNPO9BN510
footprint CAP-0603 (0603 (1608M) Capacitor)
pins: 1, 2

## CC0603GRNPO9BN560
designator C?  Capacitance: 56pF  (hidden comment: *)
Capacitor, Ceramic (MLCC), 56pF, ±2%, 50V, NP0, ±2%, SMD 0603; Manufacturer: YAGEO; Manufacturer Part Number: CC0603GRNPO9BN560
footprint CAP-0603 (0603 (1608M) Capacitor)
pins: 1, 2

## CC0603GRNPO9BN561
designator C?  Capacitance: 560pF  (hidden comment: *)
Capacitor, Ceramic (MLCC), 560pF, ±2%, 50V, NP0, ±2%, SMD 0603; Manufacturer: YAGEO; Manufacturer Part Number: CC0603GRNPO9BN561
footprint CAP-0603 (0603 (1608M) Capacitor)
pins: 1, 2

## CC0603GRNPO9BN620
designator C?  Capacitance: 62pF  (hidden comment: *)
Capacitor, Ceramic (MLCC), 62pF, ±2%, 50V, NP0, ±2%, SMD 0603; Manufacturer: YAGEO; Manufacturer Part Number: CC0603GRNPO9BN620
footprint CAP-0603 (0603 (1608M) Capacitor)
pins: 1, 2

## CC0603GRNPO9BN621
designator C?  Capacitance: 620pF  (hidden comment: *)
Capacitor, Ceramic (MLCC), 620pF, ±2%, 50V, NP0, ±2%, SMD 0603; Manufacturer: YAGEO; Manufacturer Part Number: CC0603GRNPO9BN621
footprint CAP-0603 (0603 (1608M) Capacitor)
pins: 1, 2

## CC0603GRNPO9BN680
designator C?  Capacitance: 68pF  (hidden comment: *)
Capacitor, Ceramic (MLCC), 68pF, ±2%, 50V, NP0, ±2%, SMD 0603; Manufacturer: YAGEO; Manufacturer Part Number: CC0603GRNPO9BN680
footprint CAP-0603 (0603 (1608M) Capacitor)
pins: 1, 2

## CC0603GRNPO9BN750
designator C?  Capacitance: 75pF  (hidden comment: *)
Capacitor, Ceramic (MLCC), 75pF, ±2%, 50V, NP0, ±2%, SMD 0603; Manufacturer: YAGEO; Manufacturer Part Number: CC0603GRNPO9BN750
footprint CAP-0603 (0603 (1608M) Capacitor)
pins: 1, 2

## CC0603GRNPO9BN820
designator C?  Capacitance: 82pF  (hidden comment: *)
Capacitor, Ceramic (MLCC), 82pF, ±2%, 50V, NP0, ±2%, SMD 0603; Manufacturer: YAGEO; Manufacturer Part Number: CC0603GRNPO9BN820
footprint CAP-0603 (0603 (1608M) Capacitor)
pins: 1, 2

## CC0603GRNPO9BN821
designator C?  Capacitance: 820pF  (hidden comment: *)
Capacitor, Ceramic (MLCC), 820pF, ±2%, 50V, NP0, ±2%, SMD 0603; Manufacturer: YAGEO; Manufacturer Part Number: CC0603GRNPO9BN821
footprint CAP-0603 (0603 (1608M) Capacitor)
pins: 1, 2

## CC0603JRNPO0BN100
designator C?  Capacitance: 10pF  (hidden comment: *)
Capacitor, Ceramic (MLCC), 10pF, ±5%, 100V, NP0, ±5%, SMD 0603; Manufacturer: YAGEO; Manufacturer Part Number: CC0603JRNPO0BN100
footprint CAP-0603 (0603 (1608M) Capacitor)
pins: 1, 2

## CC0603JRNPO0BN101
designator C?  Capacitance: 100pF  (hidden comment: *)
Capacitor, Ceramic (MLCC), 100pF, ±5%, 100V, NP0, ±5%, SMD 0603; Manufacturer: YAGEO; Manufacturer Part Number: CC0603JRNPO0BN101
footprint CAP-0603 (0603 (1608M) Capacitor)
pins: 1, 2

## CC0603JRNPO0BN102
designator C?  Capacitance: 1nF  (hidden comment: *)
Capacitor, Ceramic (MLCC), 1nF, ±5%, 100V, NP0, ±5%, SMD 0603; Manufacturer: YAGEO; Manufacturer Part Number: CC0603JRNPO0BN102
footprint CAP-0603 (0603 (1608M) Capacitor)
pins: 1, 2

## CC0603JRNPO0BN121
designator C?  Capacitance: 120pF  (hidden comment: *)
Capacitor, Ceramic (MLCC), 120pF, ±5%, 100V, NP0, ±5%, SMD 0603; Manufacturer: YAGEO; Manufacturer Part Number: CC0603JRNPO0BN121
footprint CAP-0603 (0603 (1608M) Capacitor)
pins: 1, 2

## CC0603JRNPO0BN150
designator C?  Capacitance: 15pF  (hidden comment: *)
Capacitor, Ceramic (MLCC), 15pF, ±5%, 100V, NP0, ±5%, SMD 0603; Manufacturer: YAGEO; Manufacturer Part Number: CC0603JRNPO0BN150
footprint CAP-0603 (0603 (1608M) Capacitor)
pins: 1, 2

## CC0603JRNPO0BN151
designator C?  Capacitance: 150pF  (hidden comment: *)
Capacitor, Ceramic (MLCC), 150pF, ±5%, 100V, NP0, ±5%, SMD 0603; Manufacturer: YAGEO; Manufacturer Part Number: CC0603JRNPO0BN151
footprint CAP-0603 (0603 (1608M) Capacitor)
pins: 1, 2

## CC0603JRNPO0BN160
designator C?  Capacitance: 16pF  (hidden comment: *)
Capacitor, Ceramic (MLCC), 16pF, ±5%, 100V, NP0, ±5%, SMD 0603; Manufacturer: YAGEO; Manufacturer Part Number: CC0603JRNPO0BN160
footprint CAP-0603 (0603 (1608M) Capacitor)
pins: 1, 2

## CC0603JRNPO0BN181
designator C?  Capacitance: 180pF  (hidden comment: *)
Capacitor, Ceramic (MLCC), 180pF, ±5%, 100V, NP0, ±5%, SMD 0603; Manufacturer: YAGEO; Manufacturer Part Number: CC0603JRNPO0BN181
footprint CAP-0603 (0603 (1608M) Capacitor)
pins: 1, 2

## CC0603JRNPO0BN200
designator C?  Capacitance: 20pF  (hidden comment: *)
Capacitor, Ceramic (MLCC), 20pF, ±5%, 100V, NP0, ±5%, SMD 0603; Manufacturer: YAGEO; Manufacturer Part Number: CC0603JRNPO0BN200
footprint CAP-0603 (0603 (1608M) Capacitor)
pins: 1, 2

## CC0603JRNPO0BN220
designator C?  Capacitance: 22pF  (hidden comment: *)
Capacitor, Ceramic (MLCC), 22pF, ±5%, 100V, NP0, ±5%, SMD 0603; Manufacturer: YAGEO; Manufacturer Part Number: CC0603JRNPO0BN220
footprint CAP-0603 (0603 (1608M) Capacitor)
pins: 1, 2

## CC0603JRNPO0BN221
designator C?  Capacitance: 220pF  (hidden comment: *)
Capacitor, Ceramic (MLCC), 220pF, ±5%, 100V, NP0, ±5%, SMD 0603; Manufacturer: YAGEO; Manufacturer Part Number: CC0603JRNPO0BN221
footprint CAP-0603 (0603 (1608M) Capacitor)
pins: 1, 2

## CC0603JRNPO0BN331
designator C?  Capacitance: 330pF  (hidden comment: *)
Capacitor, Ceramic (MLCC), 330pF, ±5%, 100V, NP0, ±5%, SMD 0603; Manufacturer: YAGEO; Manufacturer Part Number: CC0603JRNPO0BN331
footprint CAP-0603 (0603 (1608M) Capacitor)
pins: 1, 2

## CC0603JRNPO0BN360
designator C?  Capacitance: 36pF  (hidden comment: *)
Capacitor, Ceramic (MLCC), 36pF, ±5%, 100V, NP0, ±5%, SMD 0603; Manufacturer: YAGEO; Manufacturer Part Number: CC0603JRNPO0BN360
footprint CAP-0603 (0603 (1608M) Capacitor)
pins: 1, 2

## CC0603JRNPO0BN390
designator C?  Capacitance: 39pF  (hidden comment: *)
Capacitor, Ceramic (MLCC), 39pF, ±5%, 100V, NP0, ±5%, SMD 0603; Manufacturer: YAGEO; Manufacturer Part Number: CC0603JRNPO0BN390
footprint CAP-0603 (0603 (1608M) Capacitor)
pins: 1, 2

## CC0603JRNPO0BN470
designator C?  Capacitance: 47pF  (hidden comment: *)
Capacitor, Ceramic (MLCC), 47pF, ±5%, 100V, NP0, ±5%, SMD 0603; Manufacturer: YAGEO; Manufacturer Part Number: CC0603JRNPO0BN470
footprint CAP-0603 (0603 (1608M) Capacitor)
pins: 1, 2

## CC0603JRNPO0BN471
designator C?  Capacitance: 470pF  (hidden comment: *)
Capacitor, Ceramic (MLCC), 470pF, ±5%, 100V, NP0, ±5%, SMD 0603; Manufacturer: YAGEO; Manufacturer Part Number: CC0603JRNPO0BN471
footprint CAP-0603 (0603 (1608M) Capacitor)
pins: 1, 2

## CC0603JRNPO0BN510
designator C?  Capacitance: 51pF  (hidden comment: *)
Capacitor, Ceramic (MLCC), 51pF, ±5%, 100V, NP0, ±5%, SMD 0603; Manufacturer: YAGEO; Manufacturer Part Number: CC0603JRNPO0BN510
footprint CAP-0603 (0603 (1608M) Capacitor)
pins: 1, 2

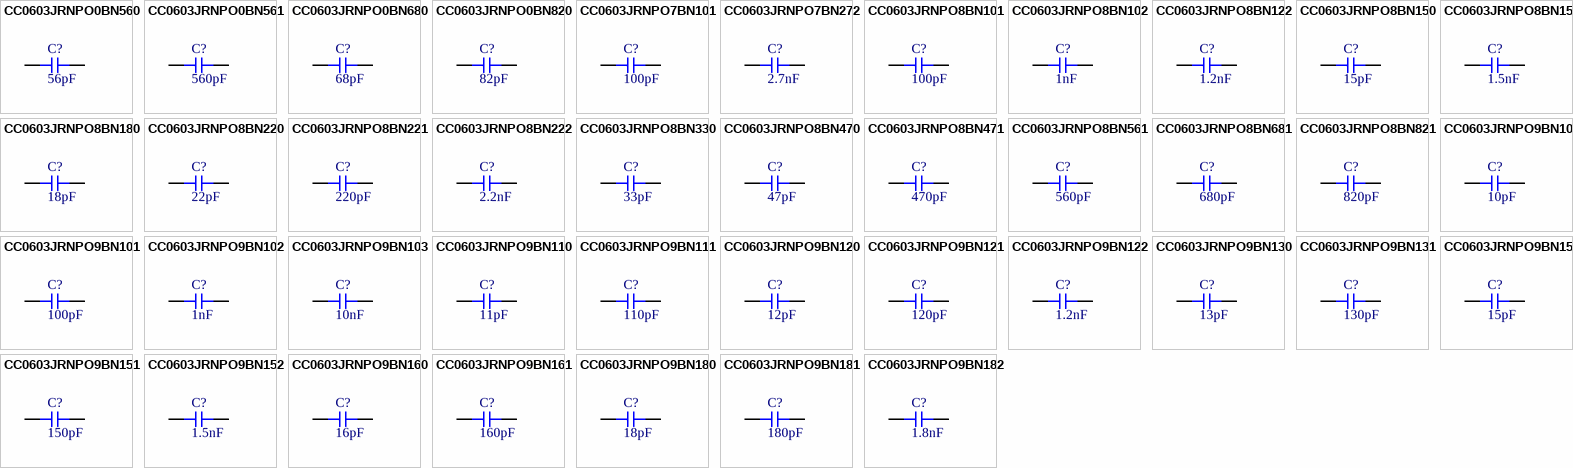
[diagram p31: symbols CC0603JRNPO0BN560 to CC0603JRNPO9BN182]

## CC0603JRNPO0BN560
designator C?  Capacitance: 56pF  (hidden comment: *)
Capacitor, Ceramic (MLCC), 56pF, ±5%, 100V, NP0, ±5%, SMD 0603; Manufacturer: YAGEO; Manufacturer Part Number: CC0603JRNPO0BN560
footprint CAP-0603 (0603 (1608M) Capacitor)
pins: 1, 2

## CC0603JRNPO0BN561
designator C?  Capacitance: 560pF  (hidden comment: *)
Capacitor, Ceramic (MLCC), 560pF, ±5%, 100V, NP0, ±5%, SMD 0603; Manufacturer: YAGEO; Manufacturer Part Number: CC0603JRNPO0BN561
footprint CAP-0603 (0603 (1608M) Capacitor)
pins: 1, 2

## CC0603JRNPO0BN680
designator C?  Capacitance: 68pF  (hidden comment: *)
Capacitor, Ceramic (MLCC), 68pF, ±5%, 100V, NP0, ±5%, SMD 0603; Manufacturer: YAGEO; Manufacturer Part Number: CC0603JRNPO0BN680
footprint CAP-0603 (0603 (1608M) Capacitor)
pins: 1, 2

## CC0603JRNPO0BN820
designator C?  Capacitance: 82pF  (hidden comment: *)
Capacitor, Ceramic (MLCC), 82pF, ±5%, 100V, NP0, ±5%, SMD 0603; Manufacturer: YAGEO; Manufacturer Part Number: CC0603JRNPO0BN820
footprint CAP-0603 (0603 (1608M) Capacitor)
pins: 1, 2

## CC0603JRNPO7BN101
designator C?  Capacitance: 100pF  (hidden comment: *)
Capacitor, Ceramic (MLCC), 100pF, ±5%, 16V, NP0, ±5%, SMD 0603; Manufacturer: YAGEO; Manufacturer Part Number: CC0603JRNPO7BN101
footprint CAP-0603 (0603 (1608M) Capacitor)
pins: 1, 2

## CC0603JRNPO7BN272
designator C?  Capacitance: 2.7nF  (hidden comment: *)
Capacitor, Ceramic (MLCC), 2.7nF, ±5%, 16V, NP0, ±5%, SMD 0603; Manufacturer: YAGEO; Manufacturer Part Number: CC0603JRNPO7BN272
footprint CAP-0603 (0603 (1608M) Capacitor)
pins: 1, 2

## CC0603JRNPO8BN101
designator C?  Capacitance: 100pF  (hidden comment: *)
Capacitor, Ceramic (MLCC), 100pF, ±5%, 25V, NP0, ±5%, SMD 0603; Manufacturer: YAGEO; Manufacturer Part Number: CC0603JRNPO8BN101
footprint CAP-0603 (0603 (1608M) Capacitor)
pins: 1, 2

## CC0603JRNPO8BN102
designator C?  Capacitance: 1nF  (hidden comment: *)
Capacitor, Ceramic (MLCC), 1nF, ±5%, 25V, NP0, ±5%, SMD 0603; Manufacturer: YAGEO; Manufacturer Part Number: CC0603JRNPO8BN102
footprint CAP-0603 (0603 (1608M) Capacitor)
pins: 1, 2

## CC0603JRNPO8BN122
designator C?  Capacitance: 1.2nF  (hidden comment: *)
Capacitor, Ceramic (MLCC), 1.2nF, ±5%, 25V, NP0, ±5%, SMD 0603; Manufacturer: YAGEO; Manufacturer Part Number: CC0603JRNPO8BN122
footprint CAP-0603 (0603 (1608M) Capacitor)
pins: 1, 2

## CC0603JRNPO8BN150
designator C?  Capacitance: 15pF  (hidden comment: *)
Capacitor, Ceramic (MLCC), 15pF, ±5%, 25V, NP0, ±5%, SMD 0603; Manufacturer: YAGEO; Manufacturer Part Number: CC0603JRNPO8BN150
footprint CAP-0603 (0603 (1608M) Capacitor)
pins: 1, 2

## CC0603JRNPO8BN152
designator C?  Capacitance: 1.5nF  (hidden comment: *)
Capacitor, Ceramic (MLCC), 1.5nF, ±5%, 25V, NP0, ±5%, SMD 0603; Manufacturer: YAGEO; Manufacturer Part Number: CC0603JRNPO8BN152
footprint CAP-0603 (0603 (1608M) Capacitor)
pins: 1, 2

## CC0603JRNPO8BN180
designator C?  Capacitance: 18pF  (hidden comment: *)
Capacitor, Ceramic (MLCC), 18pF, ±5%, 25V, NP0, ±5%, SMD 0603; Manufacturer: YAGEO; Manufacturer Part Number: CC0603JRNPO8BN180
footprint CAP-0603 (0603 (1608M) Capacitor)
pins: 1, 2

## CC0603JRNPO8BN220
designator C?  Capacitance: 22pF  (hidden comment: *)
Capacitor, Ceramic (MLCC), 22pF, ±5%, 25V, NP0, ±5%, SMD 0603; Manufacturer: YAGEO; Manufacturer Part Number: CC0603JRNPO8BN220
footprint CAP-0603 (0603 (1608M) Capacitor)
pins: 1, 2

## CC0603JRNPO8BN221
designator C?  Capacitance: 220pF  (hidden comment: *)
Capacitor, Ceramic (MLCC), 220pF, ±5%, 25V, NP0, ±5%, SMD 0603; Manufacturer: YAGEO; Manufacturer Part Number: CC0603JRNPO8BN221
footprint CAP-0603 (0603 (1608M) Capacitor)
pins: 1, 2

## CC0603JRNPO8BN222
designator C?  Capacitance: 2.2nF  (hidden comment: *)
Capacitor, Ceramic (MLCC), 2.2nF, ±5%, 25V, NP0, ±5%, SMD 0603; Manufacturer: YAGEO; Manufacturer Part Number: CC0603JRNPO8BN222
footprint CAP-0603 (0603 (1608M) Capacitor)
pins: 1, 2

## CC0603JRNPO8BN330
designator C?  Capacitance: 33pF  (hidden comment: *)
Capacitor, Ceramic (MLCC), 33pF, ±5%, 25V, NP0, ±5%, SMD 0603; Manufacturer: YAGEO; Manufacturer Part Number: CC0603JRNPO8BN330
footprint CAP-0603 (0603 (1608M) Capacitor)
pins: 1, 2

## CC0603JRNPO8BN470
designator C?  Capacitance: 47pF  (hidden comment: *)
Capacitor, Ceramic (MLCC), 47pF, ±5%, 25V, NP0, ±5%, SMD 0603; Manufacturer: YAGEO; Manufacturer Part Number: CC0603JRNPO8BN470
footprint CAP-0603 (0603 (1608M) Capacitor)
pins: 1, 2

## CC0603JRNPO8BN471
designator C?  Capacitance: 470pF  (hidden comment: *)
Capacitor, Ceramic (MLCC), 470pF, ±5%, 25V, NP0, ±5%, SMD 0603; Manufacturer: YAGEO; Manufacturer Part Number: CC0603JRNPO8BN471
footprint CAP-0603 (0603 (1608M) Capacitor)
pins: 1, 2

## CC0603JRNPO8BN561
designator C?  Capacitance: 560pF  (hidden comment: *)
Capacitor, Ceramic (MLCC), 560pF, ±5%, 25V, NP0, ±5%, SMD 0603; Manufacturer: YAGEO; Manufacturer Part Number: CC0603JRNPO8BN561
footprint CAP-0603 (0603 (1608M) Capacitor)
pins: 1, 2

## CC0603JRNPO8BN681
designator C?  Capacitance: 680pF  (hidden comment: *)
Capacitor, Ceramic (MLCC), 680pF, ±5%, 25V, NP0, ±5%, SMD 0603; Manufacturer: YAGEO; Manufacturer Part Number: CC0603JRNPO8BN681
footprint CAP-0603 (0603 (1608M) Capacitor)
pins: 1, 2

## CC0603JRNPO8BN821
designator C?  Capacitance: 820pF  (hidden comment: *)
Capacitor, Ceramic (MLCC), 820pF, ±5%, 25V, NP0, ±5%, SMD 0603; Manufacturer: YAGEO; Manufacturer Part Number: CC0603JRNPO8BN821
footprint CAP-0603 (0603 (1608M) Capacitor)
pins: 1, 2

## CC0603JRNPO9BN100
designator C?  Capacitance: 10pF  (hidden comment: *)
Capacitor, Ceramic (MLCC), 10pF, ±5%, 50V, NP0, ±5%, SMD 0603; Manufacturer: YAGEO; Manufacturer Part Number: CC0603JRNPO9BN100
footprint CAP-0603 (0603 (1608M) Capacitor)
pins: 1, 2

## CC0603JRNPO9BN101
designator C?  Capacitance: 100pF  (hidden comment: *)
Capacitor, Ceramic (MLCC), 100pF, ±5%, 50V, NP0, ±5%, SMD 0603; Manufacturer: YAGEO; Manufacturer Part Number: CC0603JRNPO9BN101
footprint CAP-0603 (0603 (1608M) Capacitor)
pins: 1, 2

## CC0603JRNPO9BN102
designator C?  Capacitance: 1nF  (hidden comment: *)
Capacitor, Ceramic (MLCC), 1nF, ±5%, 50V, NP0, ±5%, SMD 0603; Manufacturer: YAGEO; Manufacturer Part Number: CC0603JRNPO9BN102
footprint CAP-0603 (0603 (1608M) Capacitor)
pins: 1, 2

## CC0603JRNPO9BN103
designator C?  Capacitance: 10nF  (hidden comment: *)
Capacitor, Ceramic (MLCC), 10nF, ±5%, 50V, NP0, ±5%, SMD 0603; Manufacturer: YAGEO; Manufacturer Part Number: CC0603JRNPO9BN103
footprint CAP-0603 (0603 (1608M) Capacitor)
pins: 1, 2

## CC0603JRNPO9BN110
designator C?  Capacitance: 11pF  (hidden comment: *)
Capacitor, Ceramic (MLCC), 11pF, ±5%, 50V, NP0, ±5%, SMD 0603; Manufacturer: YAGEO; Manufacturer Part Number: CC0603JRNPO9BN110
footprint CAP-0603 (0603 (1608M) Capacitor)
pins: 1, 2

## CC0603JRNPO9BN111
designator C?  Capacitance: 110pF  (hidden comment: *)
Capacitor, Ceramic (MLCC), 110pF, ±5%, 50V, NP0, ±5%, SMD 0603; Manufacturer: YAGEO; Manufacturer Part Number: CC0603JRNPO9BN111
footprint CAP-0603 (0603 (1608M) Capacitor)
pins: 1, 2

## CC0603JRNPO9BN120
designator C?  Capacitance: 12pF  (hidden comment: *)
Capacitor, Ceramic (MLCC), 12pF, ±5%, 50V, NP0, ±5%, SMD 0603; Manufacturer: YAGEO; Manufacturer Part Number: CC0603JRNPO9BN120
footprint CAP-0603 (0603 (1608M) Capacitor)
pins: 1, 2

## CC0603JRNPO9BN121
designator C?  Capacitance: 120pF  (hidden comment: *)
Capacitor, Ceramic (MLCC), 120pF, ±5%, 50V, NP0, ±5%, SMD 0603; Manufacturer: YAGEO; Manufacturer Part Number: CC0603JRNPO9BN121
footprint CAP-0603 (0603 (1608M) Capacitor)
pins: 1, 2

## CC0603JRNPO9BN122
designator C?  Capacitance: 1.2nF  (hidden comment: *)
Capacitor, Ceramic (MLCC), 1.2nF, ±5%, 50V, NP0, ±5%, SMD 0603; Manufacturer: YAGEO; Manufacturer Part Number: CC0603JRNPO9BN122
footprint CAP-0603 (0603 (1608M) Capacitor)
pins: 1, 2

## CC0603JRNPO9BN130
designator C?  Capacitance: 13pF  (hidden comment: *)
Capacitor, Ceramic (MLCC), 13pF, ±5%, 50V, NP0, ±5%, SMD 0603; Manufacturer: YAGEO; Manufacturer Part Number: CC0603JRNPO9BN130
footprint CAP-0603 (0603 (1608M) Capacitor)
pins: 1, 2

## CC0603JRNPO9BN131
designator C?  Capacitance: 130pF  (hidden comment: *)
Capacitor, Ceramic (MLCC), 130pF, ±5%, 50V, NP0, ±5%, SMD 0603; Manufacturer: YAGEO; Manufacturer Part Number: CC0603JRNPO9BN131
footprint CAP-0603 (0603 (1608M) Capacitor)
pins: 1, 2

## CC0603JRNPO9BN150
designator C?  Capacitance: 15pF  (hidden comment: *)
Capacitor, Ceramic (MLCC), 15pF, ±5%, 50V, NP0, ±5%, SMD 0603; Manufacturer: YAGEO; Manufacturer Part Number: CC0603JRNPO9BN150
footprint CAP-0603 (0603 (1608M) Capacitor)
pins: 1, 2

## CC0603JRNPO9BN151
designator C?  Capacitance: 150pF  (hidden comment: *)
Capacitor, Ceramic (MLCC), 150pF, ±5%, 50V, NP0, ±5%, SMD 0603; Manufacturer: YAGEO; Manufacturer Part Number: CC0603JRNPO9BN151
footprint CAP-0603 (0603 (1608M) Capacitor)
pins: 1, 2

## CC0603JRNPO9BN152
designator C?  Capacitance: 1.5nF  (hidden comment: *)
Capacitor, Ceramic (MLCC), 1.5nF, ±5%, 50V, NP0, ±5%, SMD 0603; Manufacturer: YAGEO; Manufacturer Part Number: CC0603JRNPO9BN152
footprint CAP-0603 (0603 (1608M) Capacitor)
pins: 1, 2

## CC0603JRNPO9BN160
designator C?  Capacitance: 16pF  (hidden comment: *)
Capacitor, Ceramic (MLCC), 16pF, ±5%, 50V, NP0, ±5%, SMD 0603; Manufacturer: YAGEO; Manufacturer Part Number: CC0603JRNPO9BN160
footprint CAP-0603 (0603 (1608M) Capacitor)
pins: 1, 2

## CC0603JRNPO9BN161
designator C?  Capacitance: 160pF  (hidden comment: *)
Capacitor, Ceramic (MLCC), 160pF, ±5%, 50V, NP0, ±5%, SMD 0603; Manufacturer: YAGEO; Manufacturer Part Number: CC0603JRNPO9BN161
footprint CAP-0603 (0603 (1608M) Capacitor)
pins: 1, 2

## CC0603JRNPO9BN180
designator C?  Capacitance: 18pF  (hidden comment: *)
Capacitor, Ceramic (MLCC), 18pF, ±5%, 50V, NP0, ±5%, SMD 0603; Manufacturer: YAGEO; Manufacturer Part Number: CC0603JRNPO9BN180
footprint CAP-0603 (0603 (1608M) Capacitor)
pins: 1, 2

## CC0603JRNPO9BN181
designator C?  Capacitance: 180pF  (hidden comment: *)
Capacitor, Ceramic (MLCC), 180pF, ±5%, 50V, NP0, ±5%, SMD 0603; Manufacturer: YAGEO; Manufacturer Part Number: CC0603JRNPO9BN181
footprint CAP-0603 (0603 (1608M) Capacitor)
pins: 1, 2

## CC0603JRNPO9BN182
designator C?  Capacitance: 1.8nF  (hidden comment: *)
Capacitor, Ceramic (MLCC), 1.8nF, ±5%, 50V, NP0, ±5%, SMD 0603; Manufacturer: YAGEO; Manufacturer Part Number: CC0603JRNPO9BN182
footprint CAP-0603 (0603 (1608M) Capacitor)
pins: 1, 2

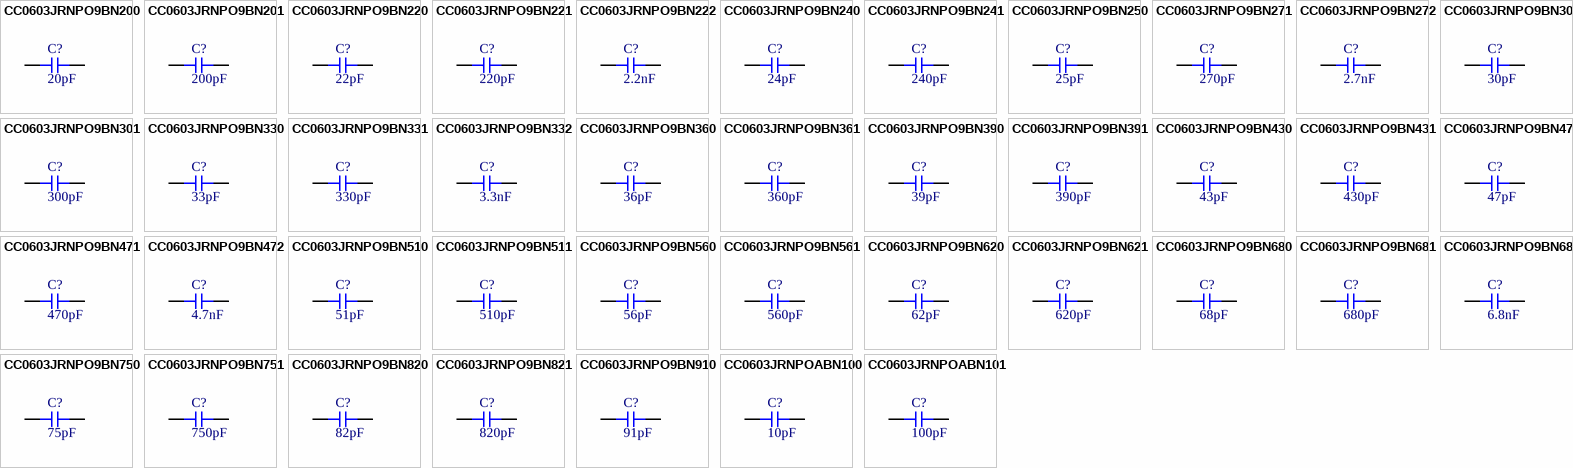
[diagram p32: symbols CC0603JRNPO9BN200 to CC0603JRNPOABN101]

## CC0603JRNPO9BN200
designator C?  Capacitance: 20pF  (hidden comment: *)
Capacitor, Ceramic (MLCC), 20pF, ±5%, 50V, NP0, ±5%, SMD 0603; Manufacturer: YAGEO; Manufacturer Part Number: CC0603JRNPO9BN200
footprint CAP-0603 (0603 (1608M) Capacitor)
pins: 1, 2

## CC0603JRNPO9BN201
designator C?  Capacitance: 200pF  (hidden comment: *)
Capacitor, Ceramic (MLCC), 200pF, ±5%, 50V, NP0, ±5%, SMD 0603; Manufacturer: YAGEO; Manufacturer Part Number: CC0603JRNPO9BN201
footprint CAP-0603 (0603 (1608M) Capacitor)
pins: 1, 2

## CC0603JRNPO9BN220
designator C?  Capacitance: 22pF  (hidden comment: *)
Capacitor, Ceramic (MLCC), 22pF, ±5%, 50V, NP0, ±5%, SMD 0603; Manufacturer: YAGEO; Manufacturer Part Number: CC0603JRNPO9BN220
footprint CAP-0603 (0603 (1608M) Capacitor)
pins: 1, 2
